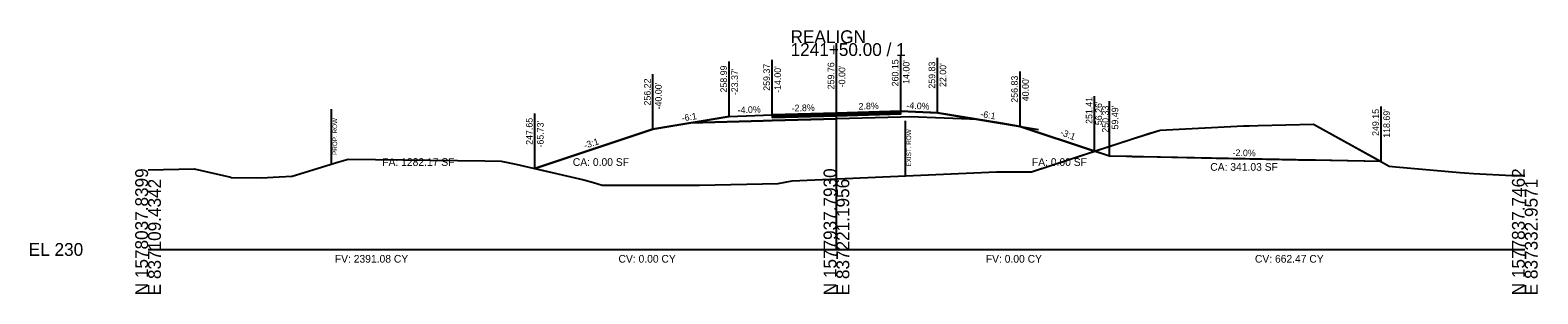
# Model space of a CAD drawing. Extents: x -26 to 6303, y -16 to 9563.
# Drawn here: x 1974.3 to 2302.8, y 1490.3 to 1547.8 of the extents above; entities that cross this region are included whole.
import ezdxf

# ---------------------------------------------------------------- set-up
doc = ezdxf.new("R2010")
doc.units = 0
for name, color, linetype in [('ASPHALT_19MM1', 7, 'Continuous'), ('ASPHALT_9_5MM1', 7, 'Continuous'), ('CONST_DCH', 7, 'Continuous'), ('CONST_LV3', 7, 'Continuous'), ('Draft_XS_Grid', 7, 'Continuous'), ('DTM_P_FINISHED_GRADE2', 7, 'Continuous'), ('DTM_TEMP_DROP', 7, 'Continuous'), ('DTM_X_GROUND', 7, 'Continuous'), ('TRANS_EOP_PAVED', 7, 'Continuous'), ('TRANS_PAVED_SHOULDERS', 7, 'Continuous'), ('XS_CELL', 7, 'Continuous'), ('XS_M_SHAPES_EARTHWORK', 7, 'Continuous'), ('XS_P_ASPHALT', 7, 'Continuous'), ('XS_P_GROUND', 7, 'Continuous'), ('XS_P_ROW', 7, 'Continuous'), ('XS_P_SHOULDER', 7, 'Continuous'), ('XS_P_SUBGRADE_GRANULAR', 7, 'Continuous'), ('XS_P_TX_CLEARZONE', 7, 'Continuous'), ('XS_P_TX_FS_BS', 7, 'Continuous'), ('XS_SHEET_EW_TX_AREA', 7, 'Continuous'), ('XS_SHEET_EW_TX_VOLUME', 7, 'Continuous'), ('XS_X_ROW', 7, 'Continuous')]:
    doc.layers.add(name, color=color, linetype=linetype)

msp = doc.modelspace()

# ---------------------------------------------------------------- linework, layer by layer
at = {"layer": 'ASPHALT_19MM1'}
msp.add_lwpolyline([(2136, 1529.03), (2136, 1528.76), (2150, 1529.16), (2150, 1529.16), (2164, 1529.55), (2164, 1529.55), (2164, 1529.82), (2164, 1529.82), (2164, 1529.82), (2150, 1529.43), (2150, 1529.43), (2136, 1529.03), (2136, 1529.03)], dxfattribs=at)
at = {"layer": 'ASPHALT_9_5MM1'}
msp.add_lwpolyline([(2136, 1529.37), (2136, 1529.24), (2150, 1529.63), (2150, 1529.63), (2164, 1530.03), (2164, 1530.03), (2164, 1530.15), (2164, 1530.15), (2164, 1530.15), (2150, 1529.76), (2150, 1529.76), (2136, 1529.37), (2136, 1529.37)], dxfattribs=at)
at = {"layer": 'CONST_LV3'}
for points in [[(2164, 1530.15), (2164, 1530.15), (2150, 1529.76)], [(2172, 1529.83), (2172, 1529.83), (2170.55, 1529.89), (2170.55, 1529.89), (2166.58, 1530.05), (2166.58, 1530.05), (2165.52, 1530.09), (2165.52, 1530.09), (2164, 1530.15)], [(2180.96, 1528.34), (2194, 1526.16)], [(2118.28, 1527.6), (2110, 1526.22)]]:
    msp.add_lwpolyline(points, dxfattribs=at)
at = {"layer": 'DTM_P_FINISHED_GRADE2'}
msp.add_lwpolyline([(2084.27, 1517.65), (2110, 1526.22), (2126.63, 1528.99), (2136, 1529.37), (2150, 1529.76), (2164, 1530.15), (2172, 1529.83)], dxfattribs=at)
at = {"layer": 'DTM_X_GROUND'}
msp.add_lwpolyline([(2000, 1517.38), (2010.05, 1517.59), (2018.01, 1515.73), (2018.05, 1515.72), (2018.08, 1515.72), (2024.7, 1515.65), (2028.57, 1515.86), (2031.39, 1516.02), (2041.58, 1519.08), (2043.63, 1519.69), (2073.36, 1519.32), (2076.93, 1519.27), (2080.11, 1518.59), (2094.99, 1515.22), (2097.06, 1514.62), (2098.95, 1514.03), (2115.61, 1514.01), (2118.36, 1514), (2120.14, 1514.05), (2137.28, 1514.39), (2140.34, 1514.98), (2184.88, 1516.96), (2191.46, 1516.94), (2192.5, 1516.93), (2218.06, 1525.26), (2220.51, 1526.05), (2224.69, 1526.25), (2238.72, 1526.97), (2239.94, 1527), (2241.92, 1527.04), (2253.99, 1527.34), (2268.78, 1519.1), (2270.42, 1518.18), (2271.89, 1518.05), (2285.86, 1516.81), (2286.84, 1516.72), (2288.82, 1516.55), (2297.2, 1516.13), (2300, 1516.1)], dxfattribs=at)
at = {"layer": 'TRANS_PAVED_SHOULDERS'}
msp.add_lwpolyline([(2136, 1529.24), (2136, 1529.03), (2150, 1529.43), (2150, 1529.43), (2164, 1529.82), (2164, 1529.82), (2164, 1530.03), (2164, 1530.03), (2164, 1530.03), (2150, 1529.63), (2150, 1529.63), (2136, 1529.24), (2136, 1529.24)], dxfattribs=at)
at = {"layer": 'XS_CELL'}
for p, q in [((2150, 1500), (2150, 1545)), ((2000, 1500), (2150, 1500)), ((2150, 1500), (2300, 1500))]:
    msp.add_line(p, q, dxfattribs=at)
at = {"layer": 'XS_M_SHAPES_EARTHWORK'}
msp.add_lwpolyline([(2084.27, 1517.65), (2094.99, 1515.22), (2097.06, 1514.62), (2098.95, 1514.03), (2115.61, 1514.01), (2118.36, 1514), (2120.14, 1514.05), (2137.28, 1514.39), (2140.34, 1514.98), (2184.88, 1516.96), (2191.46, 1516.94), (2192.5, 1516.93), (2206.26, 1521.41), (2190, 1526.83), (2180.96, 1528.34), (2166, 1528.94), (2164, 1528.88), (2150, 1528.49), (2136, 1528.1), (2134, 1528.04), (2118.28, 1527.6), (2110, 1526.22)], close=True, dxfattribs=at)
at = {"layer": 'XS_P_GROUND'}
for points in [[(2126.63, 1528.99), (2110, 1526.22), (2084.27, 1517.65)], [(2172, 1529.83), (2190, 1526.83), (2206.26, 1521.41)], [(2209.49, 1520.33), (2202.2, 1522.76), (2202.2, 1522.76), (2190, 1526.83), (2190, 1526.83), (2190, 1526.83), (2185.88, 1527.52), (2185.88, 1527.52), (2172, 1529.83)], [(2240.08, 1519.72), (2240.08, 1519.72), (2232.8, 1519.87), (2232.8, 1519.87), (2216.65, 1520.19), (2216.65, 1520.19), (2216.47, 1520.19), (2216.47, 1520.19), (2216.35, 1520.2), (2216.35, 1520.2), (2216.34, 1520.2), (2216.33, 1520.2), (2216.33, 1520.2), (2216.33, 1520.2), (2216.14, 1520.2), (2216.14, 1520.2), (2216.02, 1520.2), (2216.02, 1520.2), (2216.02, 1520.2), (2216.01, 1520.2), (2216, 1520.2), (2216, 1520.2), (2215.81, 1520.21), (2215.7, 1520.21), (2215.7, 1520.21), (2215.7, 1520.21), (2215.7, 1520.21), (2215.7, 1520.21), (2215.69, 1520.21), (2215.68, 1520.21), (2215.49, 1520.21), (2215.49, 1520.21), (2215.4, 1520.22), (2215.4, 1520.22), (2215.39, 1520.22), (2215.39, 1520.22), (2215.38, 1520.22), (2215.14, 1520.22), (2215.14, 1520.22), (2215.1, 1520.22), (2215.1, 1520.22), (2215.1, 1520.22), (2215.1, 1520.22), (2215.08, 1520.22), (2214.96, 1520.22), (2214.96, 1520.22), (2214.95, 1520.22), (2214.95, 1520.22), (2214.83, 1520.23), (2214.83, 1520.23), (2214.83, 1520.23), (2214.82, 1520.23), (2214.82, 1520.23), (2214.81, 1520.23), (2214.81, 1520.23), (2214.57, 1520.23), (2214.57, 1520.23), (2214.57, 1520.23), (2214.57, 1520.23), (2214.57, 1520.23), (2214.55, 1520.23), (2214.49, 1520.23), (2214.49, 1520.23), (2214.33, 1520.24), (2214.33, 1520.24), (2209.49, 1520.33), (2209.49, 1520.33)], [(2268.69, 1519.15), (2254.37, 1519.44), (2251.62, 1519.49), (2250.7, 1519.51), (2240.08, 1519.72)]]:
    msp.add_lwpolyline(points, dxfattribs=at)
at = {"layer": 'XS_P_ROW'}
msp.add_line((2040, 1518.61), (2040, 1530.61), dxfattribs=at)
at = {"layer": 'XS_P_SHOULDER'}
for points in [[(2126.63, 1528.99), (2136, 1529.37), (2136, 1529.37)], [(2172, 1529.83), (2164, 1530.15), (2164, 1530.15)]]:
    msp.add_lwpolyline(points, dxfattribs=at)
at = {"layer": 'XS_P_SUBGRADE_GRANULAR'}
for points in [[(2118.28, 1527.6), (2134, 1528.04), (2134, 1528.04), (2136, 1528.1), (2136, 1528.1)], [(2136, 1528.1), (2150, 1528.49), (2150, 1528.49)], [(2164, 1528.88), (2164, 1528.88), (2150, 1528.49)], [(2180.96, 1528.34), (2166, 1528.94), (2166, 1528.94), (2166, 1528.94), (2164, 1528.88)]]:
    msp.add_lwpolyline(points, dxfattribs=at)
at = {"layer": 'XS_P_TX_CLEARZONE'}
for p, q in [((2126.63, 1528.99), (2126.63, 1540.99)), ((2136, 1529.37), (2136, 1541.37)), ((2150, 1529.76), (2150, 1541.76)), ((2164, 1530.15), (2164, 1542.15)), ((2172, 1529.83), (2172, 1541.83)), ((2172, 1529.83), (2172, 1541.83)), ((2110, 1526.22), (2110, 1538.22)), ((2190, 1526.83), (2190, 1538.83)), ((2206.26, 1521.41), (2206.26, 1533.41)), ((2209.49, 1520.33), (2209.49, 1532.33)), ((2268.69, 1519.15), (2268.69, 1531.15)), ((2084.27, 1517.65), (2084.27, 1529.65))]:
    msp.add_line(p, q, dxfattribs=at)
at = {"layer": 'XS_P_TX_FS_BS'}
msp.add_lwpolyline([(2206.26, 1521.41), (2214.52, 1524.11), (2220.51, 1526.05), (2224.69, 1526.25), (2231.71, 1526.61), (2238.72, 1526.97), (2241.92, 1527.04), (2247.95, 1527.19), (2253.99, 1527.34), (2268.69, 1519.15), (2209.49, 1520.33)], close=True, dxfattribs=at)
at = {"layer": 'XS_X_ROW'}
msp.add_line((2165.08, 1516.08), (2165.08, 1528.08), dxfattribs=at)

# ---------------------------------------------------------------- texts
at = {"layer": 'CONST_DCH'}
for p in [(2135.92, 1529.25), (2149.92, 1529.64), (2163.92, 1530.03), (2209.41, 1520.21)]:
    msp.add_text('X', height=0.24, dxfattribs=at).set_placement(p)
at = {"layer": 'CONST_LV3'}
for p in [(2109.92, 1526.1), (2193.92, 1526.04)]:
    msp.add_text('X', height=0.24, dxfattribs=at).set_placement(p)
at = {"layer": 'Draft_XS_Grid'}
msp.add_text('-', height=0.0001, dxfattribs=at).set_placement((2000, 1500))
at = {"layer": 'DTM_TEMP_DROP'}
for p in [(2206.18, 1521.29), (2084.19, 1517.53)]:
    msp.add_text('X', height=0.24, dxfattribs=at).set_placement(p)
at = {"layer": 'TRANS_EOP_PAVED'}
for p in [(2171.92, 1529.71), (2189.92, 1526.71), (2206.18, 1521.29), (2084.19, 1517.53)]:
    msp.add_text('X', height=0.24, dxfattribs=at).set_placement(p)
at = {"layer": 'XS_CELL'}
for s, p in [('REALIGN', (2140, 1545)), ('1241+50.00 / 1', (2140, 1542.2)), ('EL 230', (1974, 1498.6))]:
    msp.add_text(s, height=2.8, dxfattribs=at).set_placement(p)
for s, p in [('N 1578037.8399', (2000, 1490)), ('E 837109.4342', (2002.8, 1490)), ('N 1577937.7930', (2150, 1490)), ('E 837221.1956', (2152.8, 1490)), ('N 1577837.7462', (2300, 1490)), ('E 837332.9571', (2302.8, 1490))]:
    msp.add_text(s, height=2.8, rotation=90, dxfattribs=at).set_placement(p)
at = {"layer": 'XS_P_ASPHALT'}
msp.add_text('X', height=0.24, dxfattribs=at).set_placement((2268.61, 1519.03))
at = {"layer": 'XS_P_ROW'}
msp.add_text('PROP. ROW', height=1, rotation=90, dxfattribs=at).set_placement((2041.2, 1520.61))
at = {"layer": 'XS_P_SUBGRADE_GRANULAR'}
for p in [(2126.55, 1528.87), (2171.92, 1529.71)]:
    msp.add_text('X', height=0.24, dxfattribs=at).set_placement(p)
at = {"layer": 'XS_P_TX_CLEARZONE'}
for s, p in [('260.15', (2163.52, 1535.58)), ("14.00'", (2165.92, 1536.12)), ('259.83', (2171.52, 1535.08)), ('258.99', (2126.15, 1534.23)), ("-23.37'", (2128.55, 1533.65)), ('259.37', (2135.52, 1534.61)), ("-14.00'", (2137.92, 1534.16)), ('259.76', (2149.52, 1534.93)), ("-0.00'", (2151.92, 1535.37)), ("22.00'", (2173.92, 1535.44)), ('256.83', (2189.52, 1532.01)), ('256.22', (2109.52, 1531.4)), ("-40.00'", (2111.92, 1530.54)), ("40.00'", (2191.92, 1532.33)), ('251.41', (2205.78, 1527.38)), ("56.26'", (2207.86, 1527.11)), ('250.33', (2209.33, 1525.47)), ("59.49'", (2211.41, 1526.17)), ('247.65', (2083.79, 1522.82)), ("-65.73'", (2086.19, 1522.23)), ('249.15', (2268.21, 1524.76)), ("118.69'", (2270.61, 1524.35))]:
    msp.add_text(s, height=1.44, rotation=90, dxfattribs=at).set_placement(p)
at = {"layer": 'XS_P_TX_FS_BS'}
for s, rotation, p in [('-4.0%', 2.2906, (2128.5, 1529.67)), ('-2.8%', 1.6039, (2140.25, 1530.09)), ('2.8%', 1.6039, (2154.84, 1530.5)), ('-4.0%', 357.7094, (2165.23, 1530.7)), ('-6:1', 9.4642, (2116.39, 1527.89)), ('-6:1', 350.5381, (2181.28, 1528.89)), ('-3:1', 338.8099, (2198.65, 1525)), ('-3:1', 18.4332, (2095.23, 1521.93)), ('-2.0%', 358.8542, (2236.31, 1520.4))]:
    msp.add_text(s, height=1.44, rotation=rotation, dxfattribs=at).set_placement(p)
at = {"layer": 'XS_SHEET_EW_TX_AREA'}
for s, p in [('FA: 1282.17 SF', (2051.03, 1518.22)), ('CA: 0.00 SF', (2092.56, 1518.22)), ('FA: 0.00 SF', (2192.6, 1518.22)), ('CA: 341.03 SF', (2231.46, 1517.16))]:
    msp.add_text(s, height=1.68, dxfattribs=at).set_placement(p)
at = {"layer": 'XS_SHEET_EW_TX_VOLUME'}
for s, p in [('FV: 2391.08 CY', (2040.7, 1497.12)), ('CV: 0.00 CY', (2102.51, 1497.12)), ('FV: 0.00 CY', (2182.55, 1497.12)), ('CV: 662.47 CY', (2241.19, 1497.12))]:
    msp.add_text(s, height=1.68, dxfattribs=at).set_placement(p)
at = {"layer": 'XS_X_ROW'}
msp.add_text('EXIST. ROW', height=1, rotation=90, dxfattribs=at).set_placement((2166.28, 1518.08))

doc.saveas('drawing.dxf')
